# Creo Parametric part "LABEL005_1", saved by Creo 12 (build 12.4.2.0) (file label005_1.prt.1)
Units: Custom; MM, KILOGRAM, SECS

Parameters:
  PTC_WM_ITERATION = "0"
  PTC_WM_VERSION = "-.0"
  PTC_WM_LIFECYCLE_STATE = "In Work"
  PTC_WM_LIFECYCLE = "MO_CADDocument"
  PTC_WM_CREATED_BY = "Maximilian Roepper (Z0017RMS: MO)"
  PTC_WM_CREATED_ON = "18-Sep-26 11:36:42 AM"
  PTC_WM_MODIFIED_BY = "Maximilian Roepper (Z0017RMS: MO)"
  PTC_WM_MODIFIED_ON = "18-Sep-26 11:36:46 AM"
  PDMLINKNUMBER = "PDM000071454988"
  PTC_WM_NAME = "label005_1.prt"
  PTC_WM_NUMBER = "PDM000071454988"

Other parameters: WEIGHT, WEIGHT_FACTOR, WEIGHT_ADD, _MASS_TEMP, _DIFF_TEMP, MC_ERRORS, SUPPLIER

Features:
  1. coordinate system
  2. datum plane "PRT_YZ"
  3. datum plane "PRT_XY"
  4. datum plane "PRT_XZ"
  5. coordinate system
  6. datum axis
  7. datum axis
  8. datum axis
  9. coordinate system
  10. imported feature

Other named items: PRT, SIEMENS_MO, DRW_VIEW_ORG, PRT_X, PRT_Y, PRT_Z, CS0, ROUGH_GROB

Layers: 00_STD_CSYS-KSYS, 01_STD_PLANES-EBENEN, 02_STD_AXES-ACHSEN, 03_STD_CSYS-KSYS, 24_IMPORT_FEAT-IMPORT_KE

Surfaces: 6 plane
